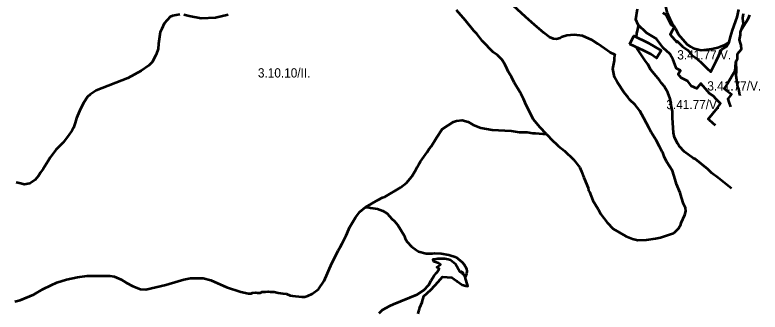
# Model space of a CAD drawing. Extents: x -555506 to -553028, y -1186750 to -1182668.
# Drawn here: x -555013 to -553409, y -1184553 to -1183913 of the extents above; entities that cross this region are included whole.
import ezdxf
from ezdxf.enums import TextEntityAlignment as Align

# ---------------------------------------------------------------- set-up
doc = ezdxf.new("R2010")
doc.units = 0
doc.header["$LTSCALE"] = 8
doc.layers.add('21', color=7, linetype='Continuous', lineweight=53)
doc.layers.add('22', color=7, linetype='Continuous')

msp = doc.modelspace()

# ---------------------------------------------------------------- linework, layer by layer
at = {"layer": '21'}
for q in [(-553454.125, -1184077.376), (-553452.56, -1184086.321)]:
    msp.add_line((-553452.877, -1184085.502), q, dxfattribs=at)
for points in [[(-553628.917, -1183866.258), (-553621.187, -1183874.75), (-553613.125, -1183891.626), (-553609.75, -1183907), (-553603.375, -1183921.375), (-553598.312, -1183932.376), (-553594.591, -1183937.571)], [(-553868.812, -1184169.375), (-553855.25, -1184183.75), (-553848, -1184190.626), (-553842.937, -1184195.626), (-553829.812, -1184205.875), (-553810.687, -1184224.501), (-553797.125, -1184241.501), (-553793.312, -1184250.001), (-553788.25, -1184263.126), (-553779.312, -1184285.501), (-553778.062, -1184290.625), (-553776.375, -1184294.001), (-553769.125, -1184312.75), (-553757.312, -1184331.375), (-553752.625, -1184341.5), (-553738.187, -1184360.126), (-553725.5, -1184373.75), (-553697.937, -1184389.376), (-553694.125, -1184390.751), (-553683.937, -1184395.001), (-553672.5, -1184397.5), (-553653.812, -1184397.126), (-553634.312, -1184394.501), (-553623.75, -1184392.376), (-553595.75, -1184383.125), (-553593.187, -1184381), (-553584.75, -1184372.5), (-553579.625, -1184364), (-553579.187, -1184360.626), (-553571.187, -1184343.625), (-553569.062, -1184335.125), (-553569.437, -1184328.376), (-553574.125, -1184319.876), (-553578.375, -1184306.375), (-553580.937, -1184296.126), (-553588.937, -1184277.501), (-553591.5, -1184267.376), (-553597.875, -1184248.626), (-553610.187, -1184228.376), (-553615.25, -1184218.125), (-553617.812, -1184211.376), (-553619.937, -1184208), (-553625.437, -1184196.125), (-553632.625, -1184182.5), (-553643.687, -1184165.626), (-553647.5, -1184157.125), (-553658.937, -1184135), (-553667.812, -1184119.751), (-553678, -1184106.25), (-553689.437, -1184096.001), (-553692.812, -1184091.001), (-553702.562, -1184079.125), (-553715.75, -1184058.751), (-553722.125, -1184046.875), (-553725.937, -1184029), (-553722.125, -1184011.251), (-553722.125, -1184006.625), (-553721.365, -1184000), (-553721.25, -1183999.001), (-553731.875, -1183994.251), (-553743.687, -1183985.376), (-553758.562, -1183975.25), (-553770.437, -1183967.626), (-553791.625, -1183958.251), (-553809.437, -1183955.75), (-553825.125, -1183957.375), (-553836.562, -1183961.251), (-553839.562, -1183962.875), (-553847.562, -1183965), (-553853.5, -1183964.626), (-553862.437, -1183960.75), (-553874.75, -1183951.5), (-553894.625, -1183934.501), (-553914.125, -1183917.501), (-553939.625, -1183893.751)], [(-554657.812, -1183912.5), (-554673.5, -1183915), (-554679, -1183917.125), (-554691.312, -1183931.5), (-554696.812, -1183943.376), (-554700.187, -1183950.251), (-554704, -1183975.626), (-554704.437, -1183985.751), (-554708.687, -1183998.501), (-554709.494, -1184000), (-554717.562, -1184015.001), (-554724.375, -1184021.876), (-554740.937, -1184033.75), (-554769.75, -1184049.376), (-554838, -1184075.751)], [(-554553.5, -1183912.875), (-554581.062, -1183919.626), (-554612, -1183920.5), (-554637.437, -1183915.876), (-554648.937, -1183912.875)], [(-553868.812, -1184169.375), (-553882.75, -1184155), (-553896.75, -1184138), (-553912.437, -1184107.501), (-553918, -1184093.876), (-553923.5, -1184083.751), (-553926, -1184078.625), (-553938.312, -1184058.25), (-553944.25, -1184046.375), (-553951.062, -1184034.625), (-553953.187, -1184029.5), (-553958.687, -1184019.251), (-553964.625, -1184009.126), (-553972.687, -1184001.126), (-553974.21, -1184000), (-553983.687, -1183993), (-554006.562, -1183969.251), (-554018.875, -1183954.001), (-554025.25, -1183947.25), (-554043.062, -1183925.125), (-554062.562, -1183903.126)], [(-553504.87, -1184151.41), (-553511.28, -1184145.17), (-553517.9, -1184139.66), (-553520.93, -1184137.34), (-553500.71, -1184112.76), (-553494.14, -1184103.94), (-553496.19, -1184101.75), (-553502.66, -1184094.84), (-553510.11, -1184086.87), (-553518.27, -1184082.2), (-553526.53, -1184072.43), (-553536.44, -1184060.69), (-553544.14, -1184069.37), (-553545.55, -1184071.44), (-553556.8, -1184066.52), (-553564.72, -1184056.02), (-553570.37, -1184053), (-553576.02, -1184049.98), (-553578.84, -1184048.47), (-553585.19, -1184040.49), (-553580.1, -1184032.43), (-553589.07, -1184028.06), (-553590.07, -1184024.62), (-553596.03, -1184009.58), (-553599.79, -1184003.27), (-553603.55, -1183996.96), (-553617.93, -1183984.14), (-553632.23, -1183964.29), (-553653.4, -1183951.97), (-553671.53, -1183934.39), (-553676.66, -1183922.68), (-553673.2, -1183899.7)], [(-553618.67, -1183908.59), (-553611.55, -1183913.18), (-553606.03, -1183923.81), (-553600.54, -1183934.49), (-553593.32, -1183938.23), (-553602.58, -1183955.5), (-553588.59, -1183971.9), (-553587.36, -1183969.84), (-553581.82, -1183975.15), (-553576.03, -1183980.7), (-553564.69, -1183989.23), (-553555.65, -1183999.65), (-553545.23, -1184006.74), (-553541.42, -1184010.2), (-553537.86, -1184013.68), (-553523.47, -1184027.78), (-553515.42, -1184035.66), (-553503.5, -1184012.68), (-553498.05, -1184000.33), (-553492.27, -1183987.37), (-553481.72, -1183980.97), (-553475.4, -1183971.52), (-553473.1, -1183960.53), (-553468.31, -1183946.22), (-553458.14, -1183917.89), (-553454.56, -1183901.72)], [(-553445.24, -1183910.57), (-553446.66, -1183920.16), (-553446.73, -1183920.6), (-553445.82, -1183932.28), (-553452.04, -1183950.11), (-553452.1, -1183956.16), (-553453.98, -1183966.85), (-553451.96, -1183974.23), (-553450.88, -1183978.18), (-553449.96, -1183987.59), (-553458.15, -1183997.82), (-553458.74, -1184008.31), (-553462.34, -1184015.28), (-553463.66, -1184033.86), (-553463.69, -1184034.17), (-553479.41, -1184060.51), (-553486.7, -1184071.27), (-553478.38, -1184077.73), (-553476.01, -1184079.57), (-553470.95, -1184083.5), (-553478.85, -1184093.36), (-553476.08, -1184101.16), (-553472.51, -1184111.2)], [(-553450.893, -1183946.821), (-553448.187, -1183943.376), (-553434.625, -1183921.375), (-553430.812, -1183912.875)], [(-553674.757, -1183961.244), (-553674.187, -1183952.75), (-553671.625, -1183940.876), (-553670.578, -1183935.313)], [(-553593.663, -1183938.869), (-553591.062, -1183942.501), (-553585.562, -1183954.375), (-553566.062, -1183976.5), (-553558.437, -1183981.625), (-553552.937, -1183984.5), (-553536, -1183989.25), (-553513.062, -1183986.251), (-553500.375, -1183983.251), (-553485.937, -1183977.751), (-553475.107, -1183970.119)], [(-553470.624, -1184286.477), (-553499.5, -1184263.5), (-553513.062, -1184253.375), (-553521.562, -1184244.875), (-553548.25, -1184223.626), (-553553.375, -1184221.125), (-553572, -1184207.5), (-553583.437, -1184195.626), (-553586, -1184190.626), (-553593.187, -1184177.001), (-553595.75, -1184166.876), (-553597.875, -1184134.626), (-553597.437, -1184121), (-553600.437, -1184107.501), (-553601.687, -1184097.376), (-553602.937, -1184093.876), (-553607.625, -1184080.375), (-553615.25, -1184066.751), (-553621.187, -1184060.001), (-553625.875, -1184053.25), (-553632.625, -1184044.75), (-553644.062, -1184031.125), (-553650.875, -1184019.251), (-553655.937, -1184012.5), (-553664.15, -1184000), (-553672.937, -1183986.625), (-553674.049, -1183983.332)], [(-553454.125, -1184077.376), (-553454.562, -1184072.75), (-553456.687, -1184068.876), (-553460.937, -1184043.501), (-553460.062, -1184035.001), (-553460.44, -1184011.601)], [(-554838, -1184075.751), (-554851.125, -1184084.626), (-554856.25, -1184089.626), (-554864.687, -1184101.5), (-554871.5, -1184115.125), (-554880, -1184135.501), (-554882.937, -1184145.626), (-554886.75, -1184155.875), (-554889.312, -1184160.875), (-554897.375, -1184172.751), (-554909.25, -1184188.001), (-554924.937, -1184203.25), (-554937.187, -1184220.251), (-554941, -1184227), (-554952.062, -1184244), (-554958, -1184252.5), (-554961.812, -1184259.25), (-554969, -1184267.75), (-554980.875, -1184276.25), (-554993.187, -1184278.001), (-555000, -1184276.126), (-555010.334, -1184273.957)], [(-554258, -1184327.125), (-554231.312, -1184311.001), (-554221.562, -1184306.375), (-554216.437, -1184304.626), (-554182.937, -1184284.75), (-554169.812, -1184274.501), (-554158.812, -1184261.001), (-554149.875, -1184246.5), (-554147.312, -1184240.625), (-554143.937, -1184235.5), (-554140.125, -1184228.751), (-554125.75, -1184208.375), (-554121.062, -1184201.625), (-554117.25, -1184196.501), (-554109.625, -1184184.625), (-554105.812, -1184177.876), (-554093.5, -1184159.25), (-554068.875, -1184143.501), (-554062.562, -1184141.001), (-554050.25, -1184139.751), (-554037.125, -1184143.126), (-554026.5, -1184149.5), (-554010.375, -1184156.251), (-553985.812, -1184160.501), (-553944.687, -1184162.626), (-553927.312, -1184165.125), (-553910.312, -1184165.626), (-553898.5, -1184167.751), (-553892.125, -1184167.751), (-553868.812, -1184169.375)], [(-555012.779, -1184530.162), (-555001.25, -1184527.25), (-554972, -1184514.5), (-554952.5, -1184503.5), (-554935.062, -1184494.626), (-554922.812, -1184489.125), (-554901.625, -1184482.25), (-554877.875, -1184477.251), (-554857.5, -1184474.626), (-554824.875, -1184474.25), (-554808.312, -1184474.626), (-554799, -1184476.375), (-554784.125, -1184482.75), (-554772.687, -1184489.876), (-554758.687, -1184497.125), (-554742.625, -1184503), (-554730.75, -1184503.875), (-554687.937, -1184494.126), (-554661.625, -1184486.126), (-554649.312, -1184482.25), (-554634.937, -1184479.751), (-554607.75, -1184479.376), (-554591.25, -1184484.001), (-554557.75, -1184499.25), (-554526.812, -1184509.375), (-554509.875, -1184512.375), (-554504.312, -1184512.375), (-554501.375, -1184511.5), (-554494.125, -1184510.75), (-554490.75, -1184511.5), (-554484, -1184511.126), (-554480.562, -1184509.375), (-554473.375, -1184509.375), (-554467.875, -1184508.125), (-554463.625, -1184509.001), (-554455.125, -1184509.001), (-554446.25, -1184511.5), (-554436.062, -1184512.375), (-554428.437, -1184513.625), (-554420.375, -1184516.625), (-554415.312, -1184517.876), (-554394.937, -1184520.001), (-554388.562, -1184519.626), (-554382.25, -1184517.876), (-554373.312, -1184513.625), (-554359.312, -1184503), (-554347.437, -1184485.251), (-554330.5, -1184447.125), (-554324.562, -1184435.251), (-554317.375, -1184420.001), (-554312.687, -1184413.126), (-554308.437, -1184404.75), (-554299.562, -1184387.751), (-554297.437, -1184382.625), (-554292.375, -1184370.751), (-554280.062, -1184348.75), (-554270.75, -1184336.876), (-554258, -1184327.125)], [(-554258, -1184327.125), (-554252.937, -1184327.125), (-554247.375, -1184328.376), (-554232.125, -1184330.125), (-554220.687, -1184334.375), (-554211.375, -1184340.25), (-554201.625, -1184352.126), (-554196.125, -1184357.25), (-554188.5, -1184365.75), (-554175.312, -1184387.751), (-554172.75, -1184394.501), (-554168.937, -1184401.25), (-554159.625, -1184411.501), (-554148.625, -1184419.125), (-554144.375, -1184422.126), (-554127.812, -1184426.376), (-554113.875, -1184426.376), (-554109.625, -1184425.5), (-554095.625, -1184426.376), (-554078.687, -1184429.75), (-554063, -1184434.376), (-554050.25, -1184445), (-554046, -1184450), (-554040.937, -1184458.5), (-554040.062, -1184465.376), (-554040.937, -1184470.376), (-554043.5, -1184477.251)], [(-554229.187, -1184554.75), (-554221.562, -1184548), (-554206.25, -1184539.5), (-554198.25, -1184535.75), (-554147.31, -1184514.88), (-554132.5, -1184505.627), (-554121.875, -1184493.75), (-554116.839, -1184484.871), (-554111.31, -1184475.131), (-554105.376, -1184468.205), (-554105.355, -1184468.18), (-554101.125, -1184463.251), (-554099.437, -1184458.5), (-554104.528, -1184455.61), (-554096.79, -1184449.95), (-554101.44, -1184447.551), (-554112.288, -1184443.791), (-554112.562, -1184439.001), (-554106.39, -1184437.97), (-554102.81, -1184437.38), (-554087.56, -1184437.38), (-554080.53, -1184438.682), (-554080.518, -1184438.684), (-554075.6, -1184440.191), (-554064.28, -1184448.611), (-554055.15, -1184464.961), (-554054.22, -1184466.62), (-554054.03, -1184466.97), (-554051.58, -1184465.63), (-554048.74, -1184470.801), (-554049.74, -1184466.72), (-554047.312, -1184472.125), (-554043.5, -1184477.251)], [(-554145.25, -1184556.501), (-554143.5, -1184549.751), (-554143.12, -1184548.98), (-554142.08, -1184544.471), (-554141.64, -1184542.541), (-554136.28, -1184531.161), (-554136.01, -1184530.22), (-554132.53, -1184518.351), (-554117.62, -1184504.841), (-554117.12, -1184504.29), (-554102.24, -1184487.861), (-554092.26, -1184476.841), (-554072.51, -1184478.291), (-554062.251, -1184485.582), (-554062.125, -1184485.626), (-554060.728, -1184486.657), (-554060.61, -1184486.74), (-554052.62, -1184492.421), (-554050.512, -1184493.922), (-554042.187, -1184496.251), (-554037.937, -1184496.751), (-554043.5, -1184477.251)]]:
    msp.add_lwpolyline(points, dxfattribs=at)
msp.add_lwpolyline([(-553689.7, -1183976.31), (-553681.07, -1183958.12), (-553650.07, -1183973.46), (-553621.85, -1183989.98), (-553632.37, -1184006.24), (-553644.53, -1183997.23), (-553658.74, -1183990.2)], close=True, dxfattribs=at)

# ---------------------------------------------------------------- texts
at = {"layer": '22', "width": 0.95}
for s, p in [('3.41.77/V.', (-553529.392, -1184009.017)), ('3.10.10/II.', (-554433.289, -1184047.8)), ('3.41.77/V.', (-553464.679, -1184075.84)), ('3.41.77/V.', (-553552.833, -1184115.903))]:
    msp.add_text(s, height=20, dxfattribs=at).set_placement(p, align=Align.CENTER)

doc.saveas('drawing.dxf')
